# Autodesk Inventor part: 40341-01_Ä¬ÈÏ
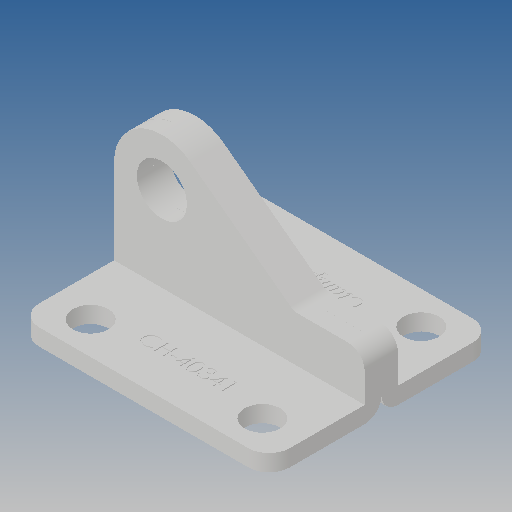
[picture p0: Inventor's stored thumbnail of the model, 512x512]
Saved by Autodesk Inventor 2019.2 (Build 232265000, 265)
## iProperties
Created: 2010-06
Part Number: 40341-01_Ä¬ÈÏ
Material: Ogólny
Document SubType Name: Modeling
Designer: CADENGINEERING4
Density: 1 g/cm^3
Appearance: Domyślna
Author: CADENGINEERING4
Revision Number: ÈÎºÎ
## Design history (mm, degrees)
feature "NONE"
feature "NONE:1"
node "Bryła1"
node "Bryła2"
